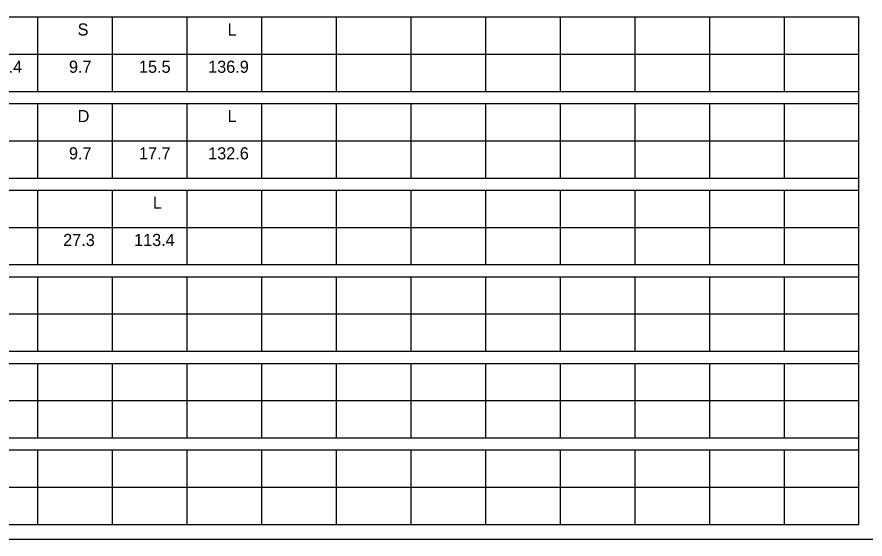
# Model space of a CAD drawing. Extents: x 121688 to 126625, y -22764 to -19972.
# Drawn here: x 125518.3 to 125846.6, y -22215.4 to -22013 of the extents above; entities that cross this region are included whole.
import ezdxf

# ---------------------------------------------------------------- set-up
doc = ezdxf.new("R2010")
doc.units = 0
doc.layers.add('GSSign', color=7, linetype='Continuous')
doc.layers.add('SheetLinesMisc2_dp', color=7, linetype='Continuous')

msp = doc.modelspace()

# ---------------------------------------------------------------- linework, layer by layer
at = {"layer": 'SheetLinesMisc2_dp'}
for p, q in [((125133.86, -22013.04), (125844.12, -22013.04)), ((125526.3, -22013.04), (125526.3, -22041.9)), ((125555.19, -22013.04), (125555.19, -22041.9)), ((125584.09, -22013.04), (125584.09, -22041.9)), ((125612.98, -22013.04), (125612.98, -22041.9)), ((125641.87, -22013.04), (125641.87, -22041.9)), ((125670.76, -22013.04), (125670.76, -22041.9)), ((125699.66, -22013.04), (125699.66, -22041.9)), ((125728.55, -22013.04), (125728.55, -22041.9)), ((125757.44, -22013.04), (125757.44, -22041.9)), ((125786.33, -22013.04), (125786.33, -22041.9)), ((125815.23, -22013.04), (125815.23, -22041.9)), ((125844.12, -22209.69), (125844.12, -22013.04)), ((125133.86, -22027.46), (125844.12, -22027.46)), ((125133.86, -22041.9), (125844.12, -22041.9)), ((125133.86, -22046.6), (125844.12, -22046.6)), ((125526.3, -22046.6), (125526.3, -22075.45)), ((125555.19, -22046.6), (125555.19, -22075.45)), ((125584.09, -22046.6), (125584.09, -22075.45)), ((125612.98, -22046.6), (125612.98, -22075.45)), ((125641.87, -22046.6), (125641.87, -22075.45)), ((125670.76, -22046.6), (125670.76, -22075.45)), ((125699.66, -22046.6), (125699.66, -22075.45)), ((125728.55, -22046.6), (125728.55, -22075.45)), ((125757.44, -22046.6), (125757.44, -22075.45)), ((125786.33, -22046.6), (125786.33, -22075.45)), ((125815.23, -22046.6), (125815.23, -22075.45)), ((125133.86, -22061.03), (125844.12, -22061.02)), ((125133.86, -22075.45), (125844.12, -22075.45)), ((125133.86, -22080.16), (125844.12, -22080.16)), ((125526.3, -22080.16), (125526.3, -22109.01)), ((125555.19, -22080.16), (125555.19, -22109.01)), ((125584.09, -22080.16), (125584.09, -22109.01)), ((125612.98, -22080.16), (125612.98, -22109.01)), ((125641.87, -22080.16), (125641.87, -22109.01)), ((125670.76, -22080.16), (125670.76, -22109.01)), ((125699.66, -22080.16), (125699.66, -22109.01)), ((125728.55, -22080.16), (125728.55, -22109.01)), ((125757.44, -22080.16), (125757.44, -22109.01)), ((125786.33, -22080.16), (125786.33, -22109.01)), ((125815.23, -22080.16), (125815.23, -22109.01)), ((125133.86, -22094.59), (125844.12, -22094.59)), ((125133.86, -22109.01), (125844.12, -22109.01)), ((125133.86, -22113.72), (125844.12, -22113.72)), ((125526.3, -22113.72), (125526.3, -22142.58)), ((125555.19, -22113.72), (125555.19, -22142.58)), ((125584.09, -22113.72), (125584.09, -22142.58)), ((125612.98, -22113.72), (125612.98, -22142.58)), ((125641.87, -22113.72), (125641.87, -22142.58)), ((125670.76, -22113.72), (125670.76, -22142.58)), ((125699.66, -22113.72), (125699.66, -22142.58)), ((125728.55, -22113.72), (125728.55, -22142.58)), ((125757.44, -22113.72), (125757.44, -22142.58)), ((125786.33, -22113.72), (125786.33, -22142.58)), ((125815.23, -22113.72), (125815.23, -22142.58)), ((125133.86, -22128.15), (125844.12, -22128.15)), ((125133.86, -22142.58), (125844.12, -22142.58)), ((125133.86, -22147.28), (125844.12, -22147.28)), ((125526.3, -22147.28), (125526.3, -22176.14)), ((125555.19, -22147.28), (125555.19, -22176.14)), ((125584.09, -22147.28), (125584.09, -22176.14)), ((125612.98, -22147.28), (125612.98, -22176.14)), ((125641.87, -22147.28), (125641.87, -22176.14)), ((125670.76, -22147.28), (125670.76, -22176.14)), ((125699.66, -22147.28), (125699.66, -22176.14)), ((125728.55, -22147.28), (125728.55, -22176.14)), ((125757.44, -22147.28), (125757.44, -22176.14)), ((125786.33, -22147.28), (125786.33, -22176.14)), ((125815.23, -22147.28), (125815.23, -22176.14)), ((125133.86, -22161.71), (125844.12, -22161.71)), ((125133.86, -22176.14), (125844.12, -22176.14)), ((125133.86, -22180.84), (125844.12, -22180.84)), ((125526.3, -22180.84), (125526.3, -22209.69)), ((125555.19, -22180.84), (125555.19, -22209.69)), ((125584.09, -22180.84), (125584.09, -22209.69)), ((125612.98, -22180.84), (125612.98, -22209.69)), ((125641.87, -22180.84), (125641.87, -22209.69)), ((125670.76, -22180.84), (125670.76, -22209.69)), ((125699.66, -22180.84), (125699.66, -22209.69)), ((125728.55, -22180.84), (125728.55, -22209.69)), ((125757.44, -22180.84), (125757.44, -22209.69)), ((125786.33, -22180.84), (125786.33, -22209.69)), ((125815.23, -22180.84), (125815.23, -22209.69)), ((125133.86, -22195.26), (125844.12, -22195.26)), ((125133.86, -22209.69), (125844.12, -22209.69)), ((125126.93, -22215.36), (126571.13, -22215.36))]:
    msp.add_line(p, q, dxfattribs=at)

# ---------------------------------------------------------------- texts
at = {"layer": 'GSSign'}
for s, height, p in [('S', 4.71, (125541.79, -22020.25)), ('L', 4.71, (125599.81, -22020.25)), ('11.4', 4.705, (125508.07, -22034.68)), ('9.7', 4.705, (125538.43, -22034.68)), ('15.5', 4.705, (125565.53, -22034.68)), ('136.9', 4.705, (125592.31, -22034.68)), ('D', 4.71, (125541.79, -22053.81)), ('L', 4.71, (125599.81, -22053.81)), ('9.7', 4.705, (125538.43, -22068.24)), ('17.7', 4.705, (125565.53, -22068.24)), ('132.6', 4.705, (125592.31, -22068.24)), ('L', 4.71, (125570.91, -22087.38)), ('27.3', 4.705, (125536.19, -22101.81)), ('113.4', 4.705, (125563.63, -22101.81))]:
    msp.add_text(s, height=height, dxfattribs=at).set_placement(p)

doc.saveas('drawing.dxf')
